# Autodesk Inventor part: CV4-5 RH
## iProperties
Created: 2005-07
Part Number: CV4-5 RH
Material: STL, A36
Document SubType Name: Modeling
Designer: clifford.barber
Manufacturer: Standard
Standards Organization: Custom
Description: Clevis Rod 1/4 x 5/16 CV4-5 RH
Item Code: CV4-5
Author: clifford.barber
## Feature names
1. Revolution1
2. Extrusion1
3. Extrusion2
4. Extrusion3
5. Chamfer1
